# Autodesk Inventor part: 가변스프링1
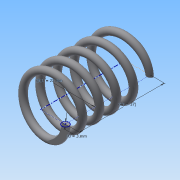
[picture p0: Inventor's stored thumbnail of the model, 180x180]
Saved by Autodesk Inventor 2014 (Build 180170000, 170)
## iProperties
Created: 2015-09
Part Number: 가변스프링1
Material: Generic
Document SubType Name: Modeling
Designer: study
Density: 1 g/cm^3
Appearance: Default
Author: study
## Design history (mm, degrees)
sketch "스케치1"
  geometry: L1 (0, 0)-(11, 0); L2 (11, 0)-(11, 37); L3 (11, 37)-(0, 37); L4 (0, 37)-(0, 0); C1 r 1.5 at (11, 0)
  constraints: 8 end point, 2 parallel, 1 centre point, 1 coincident, 1 horizontal, 1 perpendicular
  dimensions: "d0" = 3 diameter of C1; "d1" = 22 diameter of L2 L4; "d2" = 37 distance of L1.end L2.end (derived)
feature "코일1" pitch "d3" = 10; turns "d5" = 5; dims "d4" = 37 (= d2), "d6" = 0, angle "d7" = 90 deg, angle "d8" = 90 deg, "d9" = 0, "d10" = 0
node "작업 평면1"
sketch "스케치2"
  geometry: L1 (-12.5, 0)-(-9.5, 0) reference; 1 further point
  constraints: 1 horizontal alignment
extrude "돌출1" cut sketch "스케치2" stored distance "d12" = 10; taper "d13" = 0 deg
node "작업 평면2"
sketch "스케치3"
  geometry: L1 (-9.5, 0)-(-12.5, 0) reference; 1 further point
  constraints: 1 horizontal alignment
extrude "돌출2" cut sketch "스케치3" stored distance "d15" = 10; taper "d16" = 0 deg
node "솔리드1"
node "절단 모서리 투영1"
node "절단 모서리 투영2"
other parameters: "d11" = 0, "d14" = 37 (= d2)
